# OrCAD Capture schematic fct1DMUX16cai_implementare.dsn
size A
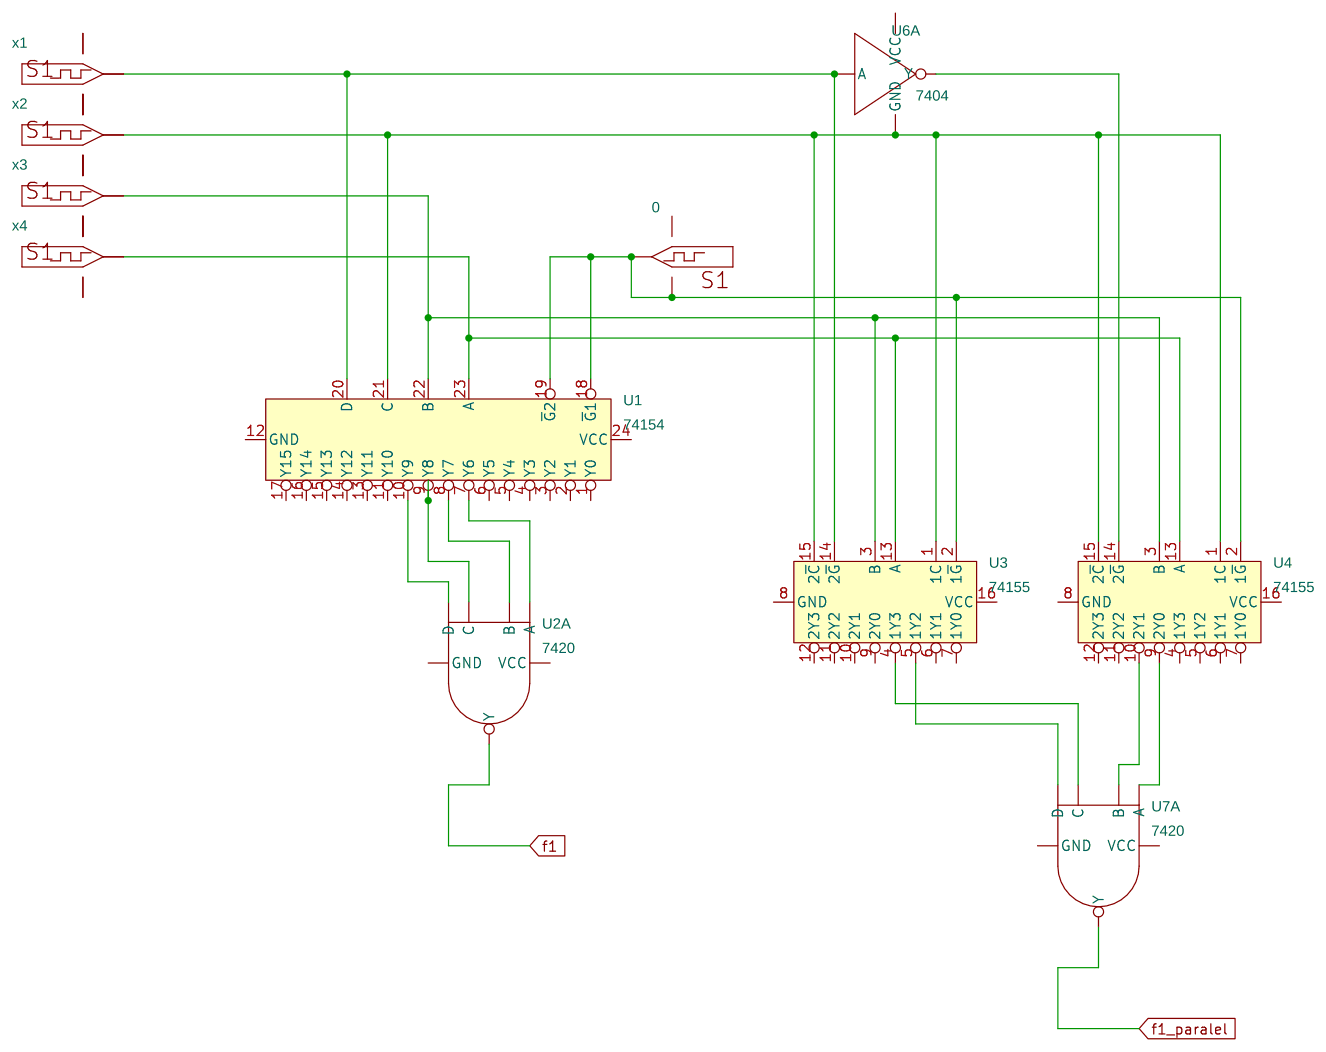
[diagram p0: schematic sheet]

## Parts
0  DigStim1
U1  74154  [DIP.100/24/W.300/L1.250]
U2  7420  [DIP.100/14/W.300/L.800]  (section A)
U3  74155  [DIP.100/16/W.300/L.900]
U4  74155  [DIP.100/16/W.300/L.900]
U6  7404  [DIP.100/14/W.300/L.800]  (section A)
U7  7420  [DIP.100/14/W.300/L.800]  (section A)
x1  DigStim1
x2  DigStim1
x3  DigStim1
x4  DigStim1

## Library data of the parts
0 x1-x4 = DigStim1
U1 = 74154
U2 U7 = 7420
U3 U4 = 74155
U6 = 7404

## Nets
GND: 0.3(GND) U1.12(GND) U2.7(GND) U3.8(GND) U4.8(GND) U6.7(GND) U7.7(GND) x1.3(GND) x2.3(GND) x3.3(GND) x4.3(GND)
VCC: 0.2(VCC) U1.24(VCC) U2.14(VCC) U3.16(VCC) U4.16(VCC) U6.14(VCC) U7.14(VCC) x1.2(VCC) x2.2(VCC) x3.2(VCC) x4.2(VCC)
f1: U2.6(Y)
f1_paralel: U7.6(Y)
N14642: 0.OUT U1.18(~{G}1) U1.19(~{G}2) U3.2(1~{G}) U4.2(1~{G})
N14674: U1.23(A) U3.13(A) U4.13(A) x4.OUT
N14681: U1.22(B) U3.3(B) U4.3(B) x3.OUT
N14692: U1.21(C) U3.1(1C) U3.15(2~{C}) U4.1(1C) U4.15(2~{C}) x2.OUT
N14699: U1.20(D) U3.14(2~{G}) U6.1(A) x1.OUT
N14810: U1.7(Y6) U2.1(A)
N14822: U1.8(Y7) U2.2(B)
N14838: U1.9(Y8) U2.4(C)
N14858: U1.10(Y9) U2.5(D)
N15880: U4.14(2~{G}) U6.2(Y)
N16123: U3.5(1Y2) U7.5(D)
N16135: U3.4(1Y3) U7.4(C)
N16153: U4.9(2Y0) U7.1(A)
N16160: U4.10(2Y1) U7.2(B)

Not connected (* = marked no-connect by the designer): U1 1(Y0) 2(Y1) 3(Y2) 4(Y3) 5(Y4) 6(Y5) 11(Y10) 13(Y11) 14(Y12) 15(Y13) 16(Y14) 17(Y15); U3 6(1Y1) 7(1Y0) 9(2Y0) 10(2Y1) 11(2Y2) 12(2Y3); U4 4(1Y3) 5(1Y2) 6(1Y1) 7(1Y0) 11(2Y2) 12(2Y3)
